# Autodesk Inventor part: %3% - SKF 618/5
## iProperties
IsCustomPart: 1
Created: 2007-02
Part Number: %3% - SKF 618/5
Material: Steel, Mild
Description: Single row ball bearings
Document SubType Name: Modeling
Standard: STN 024630 SKF
Designer: Autodesk, Inc.
Standards Organization: STN
Language: en-US
Size Designation: SKF 618/5
Categories: <MemberInstance><Categories><Category DisplayName="Shaft Parts" InternalName="7f7aeb1f-a693-4053-b835-cee3144e0d98" Mnemonic="SHFT"><Category DisplayName="Beari
Density: 7.86 g/cm^3
Mass: 1.15892 g
Surface Area: 4.73523 cm^2
Volume: 0.147446 cm^3
Author: Autodesk, Inc.
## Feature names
1. Revolution1
2. Revolution2
3. Revolution3
4. PolarArray1 [Circular Pattern]
5. Fillet1
